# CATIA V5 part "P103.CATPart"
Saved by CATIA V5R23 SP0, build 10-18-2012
Part number: P103
Definition: Support Tendeur
Bounding box of the stored display mesh (mm): x 0 to 40, y -15 to 15, z -7.956 to 26
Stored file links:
  C:\wamp\www\COURS\CONCEPTION GMP1\TITRE 02-SEMESTRE 2\03-TP7-PRESSE MECANIQUE\eleve\P103.CATPart
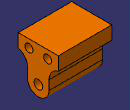
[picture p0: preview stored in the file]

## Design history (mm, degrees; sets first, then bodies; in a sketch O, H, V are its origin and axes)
Body1 (main body)
  Sketch1 on yz-plane, origin (0, 0, 0), H (0, 1, 0), V (0, 0, 1)
    point P1 (-15, 26)
    line L1 (-15, 26) -> (15, 26)
    line L2 (15, 26) -> (15, 16)
    arc A1 centre (17.2857, 7) radius 9.2857 from (15, 16) to (8, 7) ccw
    line L3 (8, 7) -> (8, 0)
    arc A2 centre (0, 0) radius 8 from (8, 0) to (-8, 0) cw
    point P7 (0, 0)
    line L4 (-8, 0) -> (-8, 7)
    arc A3 centre (-17.2857, 7) radius 9.2857 from (-8, 7) to (-15, 16) ccw
    line L5 (-15, 16) -> (-15, 26)
    point P12 (-15, 26)
    distance V L3 = 8
    distance L4 V = 8
    distance H L1 = 26
    length L1 = 30
    length L5 = 10
    length L3 = 7
    length L4 = 7
    length L2 = 10
    horizontal: L1 H
    vertical: L2 V, L5 V, L4 V
    tangency: L3 A1, A2 L3, A3 L4, A2 L4
    coincidence: P12 L1, P1 P12, P7 H
    symmetry: L5 L2 V
  Pad1: profile Sketch1, direction (1, 0, 0), length 40
  Sketch2 on face of Pad1, origin (40, 1.7009, 16), H (0, 1, 0), V (0, 0, 1)
    point P1 (5.2991, 4)
    reference projected line E1 (13.2991, 10) -> (-16.7009, 10) from edge [face of Pad1 | face of Pad1]
    reference projected line E2 (13.2991, 0) -> (13.2991, 10) from edge [face of Pad1 | face of Pad1]
    distance P1 E1 = 6
    distance P1 E2 = 8
  Hole1: placed by Sketch2, at (40, 7, 20) direction (-1, 0, 0), diameter 6, through (limit type 6)
  Mirror1: of Hole1, about zx-plane
  Sketch3 on face of Pad1, origin (40, 2.0614, 2.0487), H (0, 1, 0), V (0, 0, 1)
    point P1 (-2.0614, -2.0487)
    reference projected arc E1 centre (-2.0614, -2.0487) radius 8 from (-10.0614, -2.0487) to (5.9386, -2.0487) ccw from edge [face of Pad1 | face of Pad1]
    concentricity: P1 E1
  Hole2: placed by Sketch3, at (40, 0, 0) direction (-1, 0, 0), diameter 6.647, depth 20, V-bottom angle 120, threaded "M8", thread diameter 8, thread depth 15, pitch 1.25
